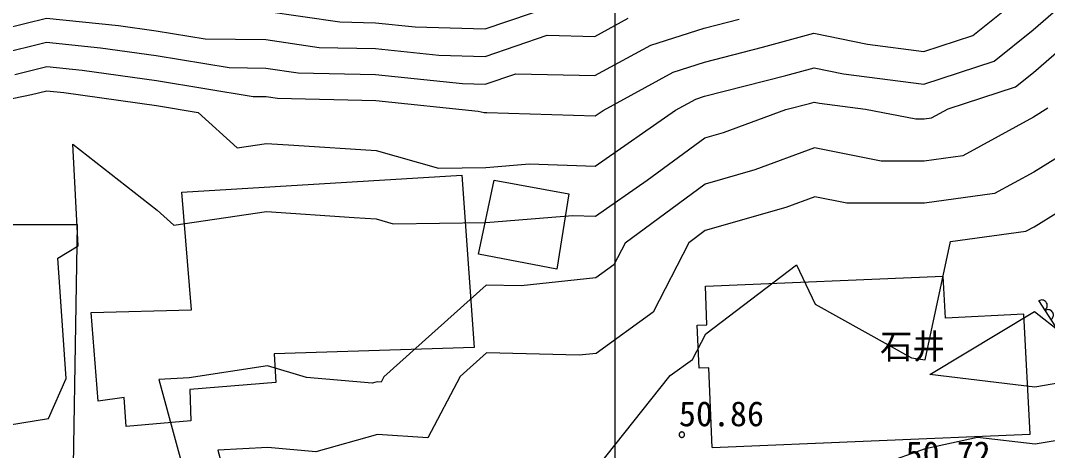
# Model space of a CAD drawing. Extents: x 42655 to 43811, y -141820 to -141156.
# Drawn here: x 43620.52 to 43668.18, y -141334.37 to -141314.41 of the extents above; entities that cross this region are included whole.
import ezdxf

# ---------------------------------------------------------------- set-up
doc = ezdxf.new("R2010")
doc.units = 0
for name, color, linetype in [('ZE_HICN', 7, 'Continuous'), ('ZE_LWCN', 7, 'Continuous'), ('地形', 7, 'Continuous')]:
    doc.layers.add(name, color=color, linetype=linetype)

msp = doc.modelspace()

# ---------------------------------------------------------------- linework, layer by layer
at = {"layer": 'ZE_HICN'}
for points in [[(43616.765, -141318.733), (43621.029, -141317.85), (43621.74, -141317.675), (43622.526, -141317.755), (43626.832, -141318.361), (43628.758, -141318.676), (43630.568, -141320.316), (43631.928, -141320.115), (43633.208, -141320.204), (43637.018, -141320.448), (43639.926, -141321.268), (43642.11, -141321.236), (43644.148, -141321.073), (43647.197, -141321.17), (43650.925, -141318.571), (43651.856, -141318.064), (43652.27, -141317.931), (43656.044, -141316.96), (43657.352, -141316.604), (43658.715, -141316.884), (43662.444, -141317.366), (43665.709, -141316.299), (43667.52, -141314.846), (43670.432, -141312.316)], [(43658.533, -141335.702), (43662.524, -141334.288), (43664.932, -141333.749), (43667.611, -141334.07), (43670.394, -141333.594)]]:
    msp.add_lwpolyline(points, dxfattribs=at)
at = {"layer": 'ZE_LWCN'}
for points in [[(43618.662, -141333.393), (43621.813, -141332.893), (43622.63, -141331.031), (43622.248, -141325.441), (43623.188, -141324.866), (43622.949, -141320.154), (43626.855, -141323.213), (43627.627, -141323.913), (43631.943, -141323.275), (43636.004, -141323.559), (43637.033, -141323.624), (43637.818, -141323.846), (43642.122, -141323.782), (43646.139, -141323.462), (43647.209, -141323.496), (43649.611, -141321.821), (43652.279, -141319.857), (43653.143, -141319.608), (43656.042, -141318.547), (43657.133, -141318.266), (43657.36, -141318.204), (43657.596, -141318.253), (43659.736, -141318.529), (43662.066, -141318.985), (43662.452, -141318.984), (43662.8, -141318.937), (43663.58, -141318.511), (43666.703, -141317.491), (43667.529, -141316.828), (43672.259, -141312.718)], [(43620.25, -141316.916), (43621.735, -141316.551), (43623.375, -141316.717), (43626.826, -141317.203), (43631.318, -141317.938), (43631.918, -141317.947), (43632.443, -141318.024), (43637.007, -141318.121), (43641.765, -141318.615), (43642.034, -141318.69), (43642.098, -141318.689), (43642.157, -141318.685), (43647.186, -141318.845), (43647.556, -141318.587), (43650.811, -141316.811), (43652.263, -141316.347), (43654.955, -141315.654), (43657.344, -141315.003), (43659.835, -141315.516), (43662.437, -141315.851), (43664.715, -141315.107), (43667.511, -141312.865)], [(43631.899, -141313.98), (43635.339, -141314.482), (43636.99, -141314.517), (43638.843, -141314.709), (43642.079, -141314.8), (43646.427, -141313.318)], [(43606.458, -141313.911), (43609.35, -141315.274), (43611.553, -141315.461), (43613.673, -141315.154), (43616.642, -141315.472), (43618.692, -141315.047), (43621.724, -141314.301), (43625.072, -141314.641), (43626.815, -141314.886), (43629.083, -141315.257), (43631.905, -141315.302), (43634.373, -141315.662), (43636.995, -141315.718), (43639.939, -141316.024), (43642.085, -141316.084), (43644.969, -141315.101), (43647.169, -141315.153), (43648.722, -141314.305)], [(43619.471, -141315.982), (43621.73, -141315.426), (43624.224, -141315.679), (43626.821, -141316.044), (43630.201, -141316.597), (43631.912, -141316.625), (43633.408, -141316.843), (43637.001, -141316.919), (43641.034, -141317.338), (43642.091, -141317.368), (43643.511, -141316.884), (43647.178, -141316.971), (43649.767, -141315.558), (43652.255, -141314.763), (43653.866, -141314.348)], [(43672.375, -141318.469), (43667.551, -141321.446), (43665.724, -141322.445), (43662.47, -141322.885), (43658.875, -141322.888), (43657.381, -141322.596), (43656.042, -141323.086), (43652.3, -141324.167), (43651.533, -141324.731), (43649.883, -141327.952), (43647.239, -141329.863), (43646.44, -141329.95), (43642.151, -141329.838), (43640.919, -141330.944), (43639.421, -141333.785), (43637.08, -141333.628), (43634.225, -141334.438), (43631.995, -141334.239), (43629.683, -141334.359), (43630.442, -141337.156), (43626.934, -141339.976), (43623.906, -141339.685), (43621.85, -141340.745), (43619.374, -141340.204)], [(43668.205, -141318.489), (43667.539, -141318.9), (43664.262, -141320.691), (43662.461, -141320.935), (43660.47, -141320.936), (43657.37, -141320.33), (43654.593, -141321.347), (43652.29, -141322.012), (43648.575, -141324.745), (43648.055, -141325.76), (43647.222, -141326.362), (43643.761, -141326.736), (43642.136, -141326.693), (43637.386, -141330.961), (43637.262, -141331.195), (43637.069, -141331.182), (43636.833, -141331.249), (43633.797, -141330.978), (43631.977, -141330.436), (43628.345, -141331.004), (43626.946, -141331.076), (43628.599, -141337.165)], [(43617.799, -141342.131), (43621.861, -141343.019), (43625.236, -141341.279), (43626.941, -141341.443), (43631.482, -141337.793), (43632.011, -141337.531), (43632.305, -141337.504), (43633.325, -141337.143), (43637.092, -141336.073), (43641.58, -141336.375), (43642.176, -141335.245), (43643.63, -141335.333), (43647.264, -141335.185), (43650.668, -141330.898), (43651.71, -141330.144), (43652.323, -141328.95), (43656.527, -141325.759), (43657.404, -141327.579), (43661.868, -141330.074), (43662.505, -141330.157), (43663.676, -141324.673), (43667.186, -141324.199), (43667.563, -141323.993), (43668.663, -141323.314)], [(43662.72, -141330.84), (43667.582, -141327.925), (43671.253, -141330.8), (43667.599, -141331.426), (43662.72, -141330.84)]]:
    msp.add_lwpolyline(points, dxfattribs=at)
at = {"layer": '地形'}
for p, q in [((43648.124, -141349.372), (43648.122, -141155.587)), ((43652.304, -141326.739), (43663.343, -141326.277)), ((43663.445, -141328.231), (43663.343, -141326.277)), ((43652.379, -141328.538), (43652.304, -141326.739)), ((43667.09, -141328.042), (43663.445, -141328.231)), ((43667.378, -141333.615), (43667.09, -141328.042)), ((43651.93, -141328.556), (43652.379, -141328.538)), ((43652.013, -141330.555), (43651.93, -141328.556)), ((43652.463, -141330.536), (43652.013, -141330.555)), ((43652.617, -141334.233), (43652.463, -141330.536)), ((43652.617, -141334.233), (43667.378, -141333.615))]:
    msp.add_line(p, q, dxfattribs=at)
for points in [[(43624.128, -141332.087), (43623.795, -141327.966), (43628.46, -141327.841), (43628.002, -141322.389), (43640.997, -141321.598), (43641.581, -141329.589), (43632.292, -141329.881), (43632.375, -141331.213), (43628.377, -141331.546), (43628.419, -141333.002), (43625.42, -141333.252), (43625.336, -141331.92), (43624.128, -141332.087)], [(43641.778, -141325.26), (43642.504, -141321.823), (43645.975, -141322.453), (43645.407, -141325.953), (43641.778, -141325.26)], [(43616.335, -141339.999), (43616.833, -141323.887), (43623.15, -141323.887), (43622.887, -141339.727), (43616.335, -141339.999)], [(43670.441, -141334.342), (43670.08, -141330.988), (43667.777, -141327.413)], [(43668.057, -141327.847), (43668.093, -141327.818), (43668.124, -141327.783), (43668.147, -141327.744), (43668.163, -141327.701), (43668.171, -141327.655), (43668.17, -141327.609), (43668.161, -141327.564), (43668.143, -141327.521), (43668.118, -141327.482), (43668.087, -141327.449), (43668.049, -141327.422), (43668.008, -141327.402), (43667.963, -141327.39), (43667.917, -141327.386), (43667.871, -141327.391), (43667.827, -141327.405), (43667.786, -141327.426)], [(43668.345, -141328.293), (43668.381, -141328.265), (43668.411, -141328.23), (43668.435, -141328.191), (43668.451, -141328.147), (43668.458, -141328.102), (43668.458, -141328.056), (43668.448, -141328.011), (43668.431, -141327.968), (43668.406, -141327.929), (43668.374, -141327.896), (43668.337, -141327.868), (43668.295, -141327.849), (43668.251, -141327.837), (43668.205, -141327.833), (43668.159, -141327.838), (43668.115, -141327.852), (43668.074, -141327.873)], [(43651.338, -141333.639), (43651.336, -141333.616), (43651.33, -141333.594), (43651.319, -141333.573), (43651.305, -141333.555), (43651.288, -141333.539), (43651.269, -141333.527), (43651.247, -141333.518), (43651.225, -141333.514), (43651.202, -141333.514), (43651.179, -141333.518), (43651.157, -141333.527), (43651.138, -141333.539), (43651.121, -141333.555), (43651.107, -141333.573), (43651.097, -141333.594), (43651.09, -141333.616), (43651.088, -141333.639)], [(43651.338, -141333.639), (43651.336, -141333.616), (43651.33, -141333.594), (43651.319, -141333.573), (43651.305, -141333.555), (43651.288, -141333.539), (43651.269, -141333.527), (43651.247, -141333.518), (43651.225, -141333.514), (43651.202, -141333.514), (43651.179, -141333.518), (43651.157, -141333.527), (43651.138, -141333.539), (43651.121, -141333.555), (43651.107, -141333.573), (43651.097, -141333.594), (43651.09, -141333.616), (43651.088, -141333.639)], [(43651.088, -141333.639), (43651.09, -141333.661), (43651.096, -141333.683), (43651.106, -141333.703), (43651.119, -141333.721), (43651.135, -141333.736), (43651.154, -141333.749), (43651.174, -141333.758), (43651.196, -141333.763), (43651.219, -141333.764), (43651.241, -141333.761), (43651.262, -141333.754), (43651.282, -141333.743), (43651.3, -141333.729), (43651.314, -141333.712), (43651.326, -141333.693), (43651.334, -141333.672), (43651.338, -141333.65), (43651.338, -141333.628), (43651.334, -141333.605), (43651.326, -141333.584), (43651.314, -141333.565), (43651.3, -141333.548), (43651.282, -141333.534), (43651.262, -141333.524), (43651.241, -141333.517), (43651.219, -141333.514), (43651.196, -141333.515), (43651.174, -141333.52), (43651.154, -141333.529), (43651.135, -141333.541), (43651.119, -141333.556), (43651.106, -141333.575), (43651.096, -141333.595), (43651.09, -141333.616), (43651.088, -141333.639)], [(43651.088, -141333.639), (43651.09, -141333.662), (43651.097, -141333.684), (43651.107, -141333.705), (43651.121, -141333.723), (43651.138, -141333.738), (43651.157, -141333.751), (43651.179, -141333.759), (43651.202, -141333.763), (43651.225, -141333.763), (43651.247, -141333.759), (43651.269, -141333.751), (43651.288, -141333.738), (43651.305, -141333.723), (43651.319, -141333.705), (43651.33, -141333.684), (43651.336, -141333.662), (43651.338, -141333.639)], [(43651.088, -141333.639), (43651.09, -141333.662), (43651.097, -141333.684), (43651.107, -141333.705), (43651.121, -141333.723), (43651.138, -141333.738), (43651.157, -141333.751), (43651.179, -141333.759), (43651.202, -141333.763), (43651.225, -141333.763), (43651.247, -141333.759), (43651.269, -141333.751), (43651.288, -141333.738), (43651.305, -141333.723), (43651.319, -141333.705), (43651.33, -141333.684), (43651.336, -141333.662), (43651.338, -141333.639)]]:
    msp.add_lwpolyline(points, dxfattribs=at)

# ---------------------------------------------------------------- texts
for s, p in [('石井', (43660.411, -141330.116)), ('50.86', (43651.077, -141333.248)), ('50.72', (43661.598, -141335.106))]:
    msp.add_text(s, height=1.1606, dxfattribs=at).set_placement(p)

doc.saveas('drawing.dxf')
